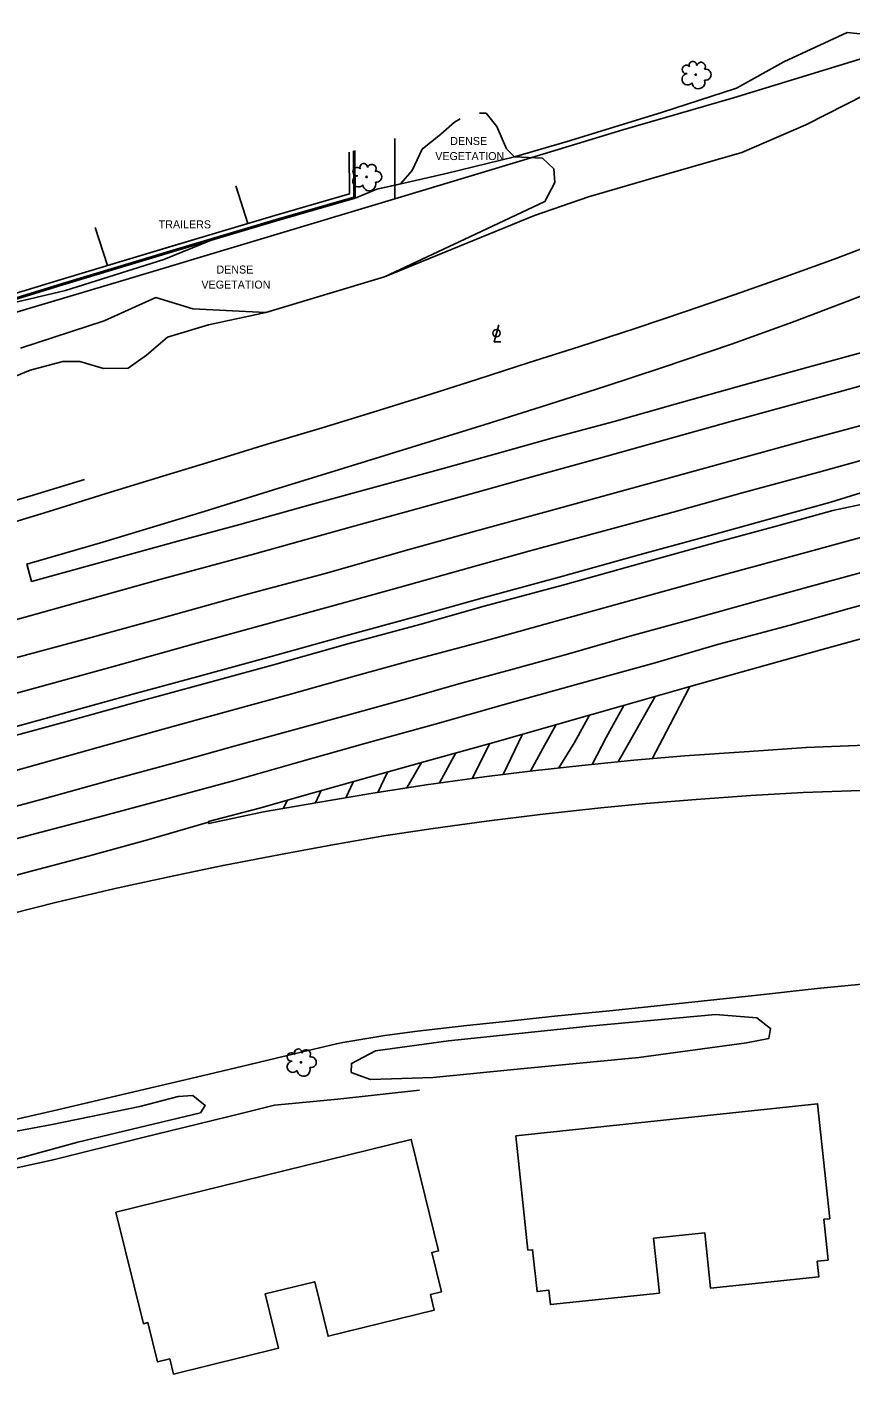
# Model space of a CAD drawing. Extents: x 2129547 to 2134906, y 657330 to 659734.
# Drawn here: x 2131098 to 2131386.1, y 657920.2 to 658391.5 of the extents above; entities that cross this region are included whole.
import ezdxf

# ---------------------------------------------------------------- set-up
doc = ezdxf.new("R2010")
doc.units = 0
for name, color, linetype in [('BD_X_Building', 7, 'Continuous'), ('DR_X_Drainage_Area', 7, 'Continuous'), ('DR_X_Paved_Gutter', 7, 'Continuous'), ('LT_X_Poles', 7, 'Continuous'), ('PM_X_Edge_Line', 7, 'Continuous'), ('PM_X_Lane_Line', 7, 'Continuous'), ('PM_X_LaneDOT', 7, 'Continuous'), ('PM_X_Transverse_Line', 7, 'Continuous'), ('PV_X_Curb', 7, 'Continuous'), ('PV_X_EOP2', 7, 'Continuous'), ('PV_X_Parking_Lot', 7, 'Continuous'), ('PV_X_Shoulder', 7, 'Continuous'), ('RD_X_Concrete_Barrier', 7, 'Continuous'), ('RD_X_Fence', 7, 'Continuous'), ('RD_X_Misc_Items', 7, 'Continuous'), ('RD_X_Noise_Wall', 7, 'Continuous'), ('VG_X_Cells', 7, 'Continuous'), ('VG_X_Text', 7, 'Continuous'), ('VG_X_Tree_Line_Lt', 7, 'Continuous')]:
    doc.layers.add(name, color=color, linetype=linetype)

# ---------------------------------------------------------------- blocks, each defined once
blk = doc.blocks.new('LPOLE')
at = {"layer": 'LT_X_Poles'}
blk.add_lwpolyline([(0.01, 0.0375), (-0.01, -0.0385), (0.02, -0.0385)], dxfattribs=at)
blk.add_circle((0, 0), 0.0165, dxfattribs=at)
blk = doc.blocks.new('TREE')
at = {"layer": 'VG_X_Cells'}
blk.add_circle((0, 0), 0.00305, dxfattribs=at)
for centre, radius, start, end in [((-0.0362, -0.0197), 0.0251, 96.17219, 320.57371), ((-0.042, 0.0237), 0.0187, 39.06254, 279.54124), ((-0.0125, 0.0428), 0.0167, 354.0047, 205.97412), ((0.0232, 0.0359), 0.0197, 323.82996, 165.0376), ((0.0439, 0.0005), 0.0243, 259.14531, 101.45961), ((0.012, -0.0331), 0.029, 184.94757, 19.45715)]:
    blk.add_arc(centre, radius, start, end, dxfattribs=at)

msp = doc.modelspace()

# ---------------------------------------------------------------- linework, layer by layer
at = {"layer": 'BD_X_Building'}
for points in [[(2131269.1, 658003.61), (2131374.7, 658014.78), (2131378.95, 657974.58), (2131376.91, 657974.37), (2131378.41, 657960.11), (2131374.58, 657959.71), (2131375.16, 657954.28), (2131337.26, 657950.27), (2131335.21, 657969.66), (2131317.3, 657967.76), (2131319.33, 657948.58), (2131281.2, 657944.54), (2131280.67, 657949.53), (2131276.51, 657949.08), (2131274.96, 657963.71), (2131273.34, 657963.53)], [(2131129.14, 657976.91), (2131232.47, 658002.32), (2131242.06, 657963.34), (2131239.75, 657962.77), (2131243.14, 657949.02), (2131239.22, 657948.06), (2131240.56, 657942.59), (2131203.41, 657933.46), (2131198.72, 657952.53), (2131181.33, 657948.26), (2131186, 657929.27), (2131149.29, 657920.24), (2131147.98, 657925.55), (2131143.68, 657924.5), (2131140.3, 657938.24), (2131138.74, 657937.86)]]:
    msp.add_lwpolyline(points, close=True, dxfattribs=at)
at = {"layer": 'DR_X_Drainage_Area'}
msp.add_lwpolyline([(2131081.23, 657985.67), (2131079.99, 657989.28), (2131107.11, 657995.18), (2131138.13, 658002.86), (2131172.93, 658011.4), (2131184.68, 658014.24), (2131206.78, 658016.4), (2131235.33, 658019.59)], dxfattribs=at)
at = {"layer": 'DR_X_Paved_Gutter'}
msp.add_lwpolyline([(2130912.03, 658255.65), (2130911.29, 658240.43), (2130925.18, 658244.78), (2130941.47, 658249.95), (2130956.68, 658254.95), (2130986.72, 658264.55), (2131016.36, 658274.11), (2131047.46, 658283.94), (2131079.63, 658293.88), (2131109.98, 658303.13), (2131149.88, 658315.14), (2131184.74, 658325.53), (2131210.86, 658333.04), (2131210.75, 658347.63)], dxfattribs=at)
at = {"layer": 'PM_X_Edge_Line'}
for points in [[(2131397.14, 658316.55), (2131380.49, 658310.25), (2131362.14, 658303.62), (2131345.56, 658297.72), (2131328.48, 658291.88), (2131311.21, 658286.08), (2131291.2, 658279.56), (2131273.71, 658274.04), (2131255.4, 658268.17), (2131237.16, 658262.34), (2131219.11, 658256.68), (2131201.27, 658251.19), (2131182.09, 658245.46), (2131162.49, 658239.45), (2131145.54, 658234.31), (2131125.68, 658228.2), (2131105.61, 658222), (2131085.18, 658215.77)], [(2131407.14, 658304.08), (2131385.87, 658295.73), (2131365.96, 658288.19), (2131344.58, 658280.53), (2131320.38, 658272.35), (2131300.22, 658265.64), (2131277.93, 658258.56), (2131258.42, 658252.41), (2131232.72, 658244.44), (2131208.93, 658237.12), (2131184.32, 658229.49), (2131159.97, 658221.99), (2131124.53, 658211.22), (2131097.92, 658203.59), (2131099.59, 658197.49), (2131122.46, 658203.72), (2131150.78, 658211.55), (2131172.55, 658217.42), (2131195.81, 658223.94), (2131222.35, 658231.18), (2131243.66, 658237.04), (2131261.8, 658242.03), (2131282.52, 658247.82), (2131303.48, 658253.47), (2131324.82, 658259.52), (2131348.96, 658266.27), (2131371.46, 658272.42), (2131394.04, 658278.67)], [(2130891, 658102.57), (2130905.36, 658106.57), (2130928.7, 658112.95), (2130952.19, 658119.5), (2130974.68, 658125.71), (2130991.22, 658130.21), (2131011.99, 658135.88), (2131037.88, 658143.01), (2131060.83, 658149.3), (2131082.78, 658155.22), (2131106.25, 658161.71), (2131128.24, 658167.69), (2131156.14, 658175.52), (2131181.21, 658182.49), (2131205.87, 658189.24), (2131228.59, 658195.53), (2131252.79, 658202.27), (2131273.67, 658208.13), (2131298.68, 658214.86), (2131324.12, 658221.75), (2131348.82, 658228.57), (2131375.1, 658235.74), (2131400.81, 658242.88)], [(2131391.93, 658213.4), (2131368, 658206.91), (2131341.78, 658199.75), (2131315.24, 658192.47), (2131285.72, 658184.3), (2131257.55, 658176.45), (2131231.68, 658169.56), (2131212.62, 658164.32), (2131190.64, 658158.19), (2131169.84, 658152.49), (2131145.7, 658145.83), (2131125.75, 658140.27), (2131100.74, 658133.28), (2131080.69, 658127.69), (2131055.04, 658120.76), (2131018.49, 658110.67), (2130998.15, 658105.13), (2130976.5, 658099.09), (2130942.37, 658089.65), (2130912.01, 658081.31), (2130898.43, 658077.6)], [(2131391.44, 658140.23), (2131370.77, 658139.37), (2131350.73, 658138.01), (2131328.18, 658136.44), (2131310.35, 658134.93), (2131292.2, 658133.12), (2131275.07, 658131.28), (2131257.97, 658129.14), (2131237.72, 658126.39), (2131218.4, 658123.33), (2131199.77, 658120.19), (2131180.79, 658116.87), (2131161.65, 658112.79), (2131161.55, 658113.24), (2131161.49, 658113.52), (2131179.33, 658118.24), (2131198.59, 658123.67), (2131221.46, 658130.06), (2131240.32, 658135.36), (2131262.27, 658141.42), (2131285.46, 658148.07), (2131305.96, 658153.83), (2131329.61, 658160.63), (2131348.33, 658165.83), (2131376.27, 658173.65), (2131406.46, 658181.91)], [(2131092.36, 658081.28), (2131108.42, 658085.27), (2131129.89, 658090.28), (2131149.34, 658094.56), (2131166.66, 658098.14), (2131186.77, 658102.01), (2131204.3, 658105.27), (2131222.86, 658108.47), (2131240.18, 658111.04), (2131258.85, 658113.61), (2131277.62, 658115.99), (2131298.88, 658118.25), (2131314.61, 658119.83), (2131332.2, 658121.23), (2131351.31, 658122.57), (2131369.66, 658123.62), (2131389.91, 658124.35)]]:
    msp.add_lwpolyline(points, dxfattribs=at)
at = {"layer": 'PM_X_Lane_Line'}
for points in [[(2130883.95, 658126.23), (2130909.74, 658133.43), (2130940.43, 658141.55), (2130966.85, 658148.84), (2130984.68, 658153.87), (2131010.49, 658161.21), (2131031.7, 658166.99), (2131053.74, 658172.98), (2131070.1, 658177.45), (2131103.99, 658186.81), (2131144.51, 658198.18), (2131177.77, 658207.11), (2131211.57, 658216.59), (2131235.4, 658223.12), (2131255.58, 658228.68), (2131276.03, 658234.43), (2131298.07, 658240.54), (2131321.32, 658247), (2131343.87, 658253.31), (2131381.41, 658263.57), (2131428.52, 658276.66)], [(2131394.23, 658253.22), (2131371.64, 658247.1), (2131347.48, 658240.52), (2131325.08, 658234.28), (2131302.56, 658228.11), (2131279.27, 658221.78), (2131255.34, 658215.2), (2131230.51, 658208.32), (2131202.78, 658200.44), (2131175.2, 658193.07), (2131142.99, 658184.04), (2131119.15, 658177.56), (2131092.27, 658170.26), (2131066.31, 658163.11), (2131037.76, 658155.51), (2131013.74, 658149.02), (2130988.03, 658141.76), (2130968.64, 658136.39), (2130940.36, 658128.62), (2130910.43, 658120.51), (2130887.53, 658114.21)], [(2131398.2, 658202.88), (2131377.59, 658197.24), (2131355.03, 658191.01), (2131329.48, 658184), (2131308.98, 658178.3), (2131287.17, 658172.05), (2131268.54, 658166.95), (2131249.14, 658161.71), (2131232.12, 658156.84), (2131210.13, 658150.71), (2131191.34, 658145.6), (2131170.47, 658139.83), (2131150.51, 658134.32), (2131128.13, 658128.26), (2131104.27, 658121.56), (2131076.93, 658114.27), (2131045.67, 658105.64), (2131023.04, 658099.46), (2131001.31, 658093.68), (2130986.21, 658089.5), (2130954.6, 658080.73), (2130930.95, 658074.11), (2130910.13, 658068.18), (2130901.91, 658065.91)], [(2131411.36, 658195.07), (2131385.77, 658188.02), (2131365.07, 658182.24), (2131339.74, 658175.46), (2131317.81, 658169.03), (2131291.94, 658161.94), (2131264.7, 658154.39), (2131240.9, 658147.6), (2131216.24, 658140.85), (2131193.46, 658134.43), (2131170.64, 658127.88), (2131144.22, 658120.81), (2131121.64, 658114.69), (2131098.02, 658108.51), (2131078.46, 658103.25), (2131054.06, 658096.57), (2131026.75, 658089.3), (2131004.3, 658082.86), (2130988.32, 658078.33), (2130961.86, 658070.94), (2130936.23, 658064.05), (2130907.59, 658055.8), (2130905.13, 658055.12)]]:
    msp.add_lwpolyline(points, dxfattribs=at)
at = {"layer": 'PM_X_LaneDOT'}
msp.add_lwpolyline([(2131007.54, 658071.14), (2131033.85, 658078.34), (2131056.59, 658084.53), (2131076.06, 658089.79), (2131097.73, 658095.69), (2131119.36, 658101.43), (2131140.64, 658107.17), (2131161.55, 658113.24)], dxfattribs=at)
at = {"layer": 'PM_X_Transverse_Line'}
for p, q in [((2131271.45, 658144.05), (2131264.64, 658129.97)), ((2131260.03, 658140.8), (2131253.8, 658128.57)), ((2131248.11, 658137.51), (2131242.35, 658127.02)), ((2131224.15, 658130.82), (2131220.81, 658123.71)), ((2131236.06, 658134.16), (2131230.98, 658125.33)), ((2131212.24, 658127.49), (2131209.64, 658121.85)), ((2131189.14, 658121.01), (2131187.68, 658118.07)), ((2131200.99, 658124.34), (2131198.93, 658120.04))]:
    msp.add_line(p, q, dxfattribs=at)
for points in [[(2131330, 658160.73), (2131323.14, 658147.43), (2131316.83, 658135.48)], [(2131306.89, 658154.1), (2131300.75, 658142.95), (2131295.82, 658133.48)], [(2131317.92, 658157.27), (2131311.17, 658145.53), (2131304.9, 658134.38)], [(2131294.9, 658150.72), (2131289.58, 658141.17), (2131284.19, 658132.26)], [(2131283.23, 658147.43), (2131278.56, 658139.03), (2131274.21, 658131.17)]]:
    msp.add_lwpolyline(points, dxfattribs=at)
at = {"layer": 'PV_X_Curb'}
msp.add_lwpolyline([(2130909.99, 658254.98), (2130909.16, 658237.67), (2130925.79, 658242.87), (2130942.09, 658248.05), (2130957.3, 658253.05), (2130979.6, 658260.17), (2130987.33, 658262.65), (2131016.97, 658272.21), (2131048.06, 658282.04), (2131080.22, 658291.97), (2131110.56, 658301.22), (2131150.45, 658313.22), (2131162.19, 658316.72), (2131185.31, 658323.61), (2131212.87, 658331.54), (2131212.75, 658347.8), (2131212.76, 658348.23)], dxfattribs=at)
at = {"layer": 'PV_X_EOP2'}
for points in [[(2131098.03, 658203.17), (2131099.59, 658197.49), (2131122.46, 658203.72), (2131150.78, 658211.55), (2131172.55, 658217.42), (2131195.81, 658223.94), (2131222.35, 658231.18), (2131243.66, 658237.04), (2131261.8, 658242.03), (2131282.52, 658247.82), (2131303.48, 658253.47), (2131324.82, 658259.52), (2131348.96, 658266.27), (2131371.46, 658272.42), (2131394.04, 658278.67)], [(2130891, 658102.57), (2130905.36, 658106.57), (2130928.7, 658112.95), (2130952.19, 658119.5), (2130974.68, 658125.71), (2130991.22, 658130.21), (2131011.99, 658135.88), (2131037.88, 658143.01), (2131060.83, 658149.3), (2131082.78, 658155.22), (2131106.25, 658161.71), (2131128.24, 658167.69), (2131156.14, 658175.52), (2131181.21, 658182.49), (2131205.87, 658189.24), (2131228.59, 658195.53), (2131252.79, 658202.27), (2131273.67, 658208.13), (2131298.68, 658214.86), (2131324.12, 658221.75), (2131348.82, 658228.57), (2131375.1, 658235.74), (2131400.81, 658242.88)], [(2131391.93, 658213.4), (2131368, 658206.91), (2131341.78, 658199.75), (2131315.24, 658192.47), (2131285.72, 658184.3), (2131257.55, 658176.45), (2131231.68, 658169.56), (2131212.62, 658164.32), (2131190.64, 658158.19), (2131169.84, 658152.49), (2131145.7, 658145.83), (2131125.75, 658140.27), (2131100.74, 658133.28), (2131080.69, 658127.69), (2131055.04, 658120.76), (2131018.49, 658110.67), (2130998.15, 658105.13), (2130976.5, 658099.09), (2130942.37, 658089.65), (2130912.01, 658081.31), (2130898.43, 658077.6)], [(2131161.63, 658112.89), (2131161.55, 658113.24), (2131161.49, 658113.52), (2131179.33, 658118.24), (2131198.59, 658123.67), (2131221.46, 658130.06), (2131240.32, 658135.36), (2131262.27, 658141.42), (2131285.46, 658148.07), (2131305.96, 658153.83), (2131329.61, 658160.63), (2131348.33, 658165.83), (2131376.27, 658173.65), (2131406.46, 658181.91)], [(2130911.96, 658032.18), (2130933.97, 658038.2), (2130961.85, 658045.78), (2130991.21, 658053.76), (2131010.83, 658059.23), (2131028.09, 658064.06), (2131048.8, 658069.77), (2131070.04, 658075.58), (2131092.36, 658081.28), (2131108.42, 658085.27), (2131129.89, 658090.28), (2131149.34, 658094.56), (2131164.37, 658097.66)]]:
    msp.add_lwpolyline(points, dxfattribs=at)
at = {"layer": 'PV_X_Parking_Lot'}
msp.add_lwpolyline([(2130910.5, 658255.15), (2130909.69, 658238.36), (2130925.63, 658243.35), (2130941.93, 658248.53), (2130957.14, 658253.52), (2130987.18, 658263.12), (2131016.82, 658272.69), (2131047.9, 658282.51), (2131080.06, 658292.44), (2131110.42, 658301.69), (2131150.31, 658313.7), (2131185.17, 658324.09), (2131212.36, 658331.91), (2131212.25, 658347.81), (2131212.25, 658348.08)], dxfattribs=at)
at = {"layer": 'PV_X_Shoulder'}
msp.add_lwpolyline([(2131118.09, 658233.1), (2131098.99, 658227.31), (2131081.01, 658222.02), (2131059.09, 658215.24), (2131035.24, 658208.02), (2131014.76, 658201.93), (2130993.74, 658195.63), (2130974.74, 658189.85), (2130961.01, 658185.65), (2130936.73, 658178.19), (2130914.43, 658171.83), (2130889.82, 658164.49), (2130873.95, 658159.78)], dxfattribs=at)
at = {"layer": 'RD_X_Concrete_Barrier'}
for points in [[(2131391.74, 658229.13), (2131379.32, 658225.19), (2131359.92, 658219.83), (2131338.36, 658213.96), (2131312.24, 658206.8), (2131285.52, 658199.37), (2131257.25, 658191.69), (2131234.72, 658185.34), (2131209.47, 658178.52), (2131183.51, 658171.23), (2131159.15, 658164.59), (2131135.07, 658158.08), (2131111.97, 658151.63), (2131085.68, 658144.48), (2131061.03, 658137.57), (2131037, 658130.96), (2131013.95, 658124.67), (2130994.29, 658119.1), (2130982.69, 658115.91), (2130954.42, 658108.17), (2130930.56, 658101.55), (2130905.86, 658094.77), (2130894.27, 658091.58)], [(2130895.13, 658088.7), (2130906.66, 658091.87), (2130931.36, 658098.66), (2130955.21, 658105.28), (2130983.48, 658113.02), (2130995.09, 658116.21), (2131014.76, 658121.78), (2131037.79, 658128.06), (2131061.83, 658134.68), (2131086.48, 658141.59), (2131112.76, 658148.74), (2131135.87, 658155.19), (2131159.93, 658161.69), (2131184.31, 658168.34), (2131210.27, 658175.63), (2131235.52, 658182.45), (2131258.05, 658188.8), (2131286.32, 658196.47), (2131313.04, 658203.91), (2131339.15, 658211.07), (2131360.71, 658216.94), (2131380.03, 658222.28), (2131393.19, 658225.09)]]:
    msp.add_lwpolyline(points, dxfattribs=at)
at = {"layer": 'RD_X_Fence'}
for points in [[(2131226.74, 658331.31), (2131270.47, 658344.48), (2131306.54, 658355.42), (2131345.29, 658366.68), (2131388.04, 658379.77), (2131421.48, 658390.1), (2131443.08, 658403.45), (2131490.2, 658433.33), (2131529.88, 658458.13), (2131570.9, 658483.93), (2131597.76, 658501.09), (2131622.97, 658531.22), (2131648.63, 658561.86), (2131672.4, 658590.57), (2131696.88, 658620.08), (2131710.47, 658636.49)], [(2130958.33, 658249.24), (2131021.99, 658269.61), (2131092.36, 658291.14), (2131130.38, 658302.4), (2131226.74, 658331.31), (2131226.8, 658352.41)]]:
    msp.add_lwpolyline(points, dxfattribs=at)
at = {"layer": 'RD_X_Misc_Items'}
for points in [[(2131212.87, 658331.54), (2131220.44, 658334.66), (2131225.82, 658335.88), (2131244.66, 658340.15), (2131268.67, 658345.98), (2131278.42, 658345.56), (2131282.42, 658341.79), (2131282.76, 658337.06), (2131279.3, 658330.41), (2131255.01, 658318.95), (2131223.11, 658304.02), (2131181.57, 658291.62), (2131156.06, 658292.91), (2131143.05, 658296.77), (2131125.02, 658288.63), (2131095.68, 658279.05)], [(2131171.11, 658335.91), (2131175.24, 658322.7), (2131126.14, 658307.99), (2131121.88, 658321.35)], [(2130857.88, 658213.75), (2130866.51, 658217.26), (2130886.93, 658224.32), (2130903.66, 658230.77), (2130919.66, 658236.04), (2130945.37, 658244.73), (2130958.47, 658248.73), (2130979.6, 658260.17), (2130987.33, 658262.65), (2131016.97, 658272.21), (2131048.06, 658282.04), (2131080.22, 658291.97), (2131111.51, 658299.3), (2131145.88, 658310.07), (2131162.19, 658316.72), (2131185.31, 658323.61), (2131212.87, 658331.54)]]:
    msp.add_lwpolyline(points, dxfattribs=at)
at = {"layer": 'RD_X_Noise_Wall'}
msp.add_lwpolyline([(2130931.96, 657970.88), (2130980.32, 657982.07), (2131028.87, 657993.85), (2131057.77, 658000.57), (2131076.18, 658004.83), (2131090.82, 658008.54), (2131108.69, 658012.68), (2131119.07, 658015.09), (2131137.42, 658019.48), (2131157.38, 658024.08), (2131175.99, 658028.56), (2131194.4, 658032.9), (2131206.33, 658035.77), (2131208.58, 658036.27), (2131223.29, 658038.63), (2131234.65, 658040.24), (2131251.99, 658042.15), (2131266.67, 658043.72), (2131282.64, 658045.38), (2131301.91, 658047.28), (2131315.35, 658048.67), (2131352.59, 658052.69), (2131374.52, 658055.12), (2131396.24, 658057.26)], dxfattribs=at)
at = {"layer": 'VG_X_Tree_Line_Lt'}
for points in [[(2131256.42, 658361.32), (2131258.71, 658361.28), (2131262.42, 658356.63), (2131265.81, 658348.84), (2131268.67, 658345.98), (2131287.05, 658351.41), (2131320.12, 658361.57), (2131346.37, 658370.07), (2131362.85, 658379.31), (2131385.08, 658389.49), (2131399.78, 658388.04)], [(2131391.44, 658367.82), (2131370.64, 658357.17), (2131348.25, 658347.51), (2131321.04, 658339.69), (2131294.5, 658332.06), (2131275.63, 658325.51), (2131223.11, 658304.02), (2131181.57, 658291.62), (2131161.57, 658287.22), (2131147.2, 658282.92), (2131139.83, 658276.66), (2131133.41, 658272.14), (2131124.82, 658271.95), (2131116.45, 658274.38), (2131110.59, 658274.4), (2131099.07, 658271.37), (2131080.92, 658263.98)], [(2131080.22, 658291.97), (2131111.51, 658299.3), (2131145.88, 658310.07), (2131162.19, 658316.72), (2131185.31, 658323.61), (2131212.87, 658331.54), (2131220.44, 658334.66), (2131228.74, 658336.55), (2131232.85, 658341.25), (2131236.35, 658348.68), (2131242.86, 658353.9), (2131247.69, 658358.13), (2131249.6, 658359.27)], [(2131106.84, 658007.5), (2131137.48, 658013.79), (2131150.96, 658017.34), (2131156.06, 658017.66), (2131160.36, 658014.23), (2131158.71, 658011.58), (2131115.74, 658001.37), (2131092.01, 657994.84), (2131077.49, 657991.38), (2131065.97, 657989.24), (2131044.21, 657985.16), (2131040.57, 657987.06), (2131039.11, 657991.16), (2131046.06, 657994.02), (2131089.93, 658004.34), (2131106.84, 658007.5)]]:
    msp.add_lwpolyline(points, dxfattribs=at)
msp.add_lwpolyline([(2131269.52, 658026.89), (2131240.12, 658024.01), (2131218.2, 658023.31), (2131211.48, 658025.74), (2131211.56, 658028.89), (2131220.01, 658033.27), (2131245.57, 658036.8), (2131294.8, 658041.92), (2131339.01, 658046.05), (2131353.5, 658044.84), (2131358.25, 658041.14), (2131357.64, 658037.61), (2131349.87, 658036.09), (2131312.16, 658030.95)], close=True, dxfattribs=at)

# ---------------------------------------------------------------- block references
at = {"layer": 'LT_X_Poles', "xscale": 78.74000000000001, "yscale": 78.74000000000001}
msp.add_blockref('LPOLE', (2131262.33, 658284.36), dxfattribs=at)
at = {"layer": 'VG_X_Cells', "xscale": 78.74000000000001, "yscale": 78.74000000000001}
for p in [(2131332.08, 658374.72), (2131216.84, 658339.02), (2131193.87, 658029.28)]:
    msp.add_blockref('TREE', p, dxfattribs=at)

# ---------------------------------------------------------------- texts
at = {"layer": 'RD_X_Misc_Items'}
msp.add_text('TRAILERS', height=2.8, dxfattribs=at).set_placement((2131144.1, 658321))
at = {"layer": 'VG_X_Text'}
for s, p in [('DENSE', (2131246.14, 658350.16)), ('VEGETATION', (2131240.9, 658344.89)), ('DENSE', (2131164.31, 658305.2)), ('VEGETATION', (2131159.06, 658299.93))]:
    msp.add_text(s, height=2.8, dxfattribs=at).set_placement(p)

doc.saveas('drawing.dxf')
